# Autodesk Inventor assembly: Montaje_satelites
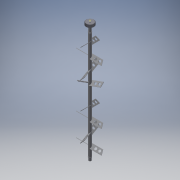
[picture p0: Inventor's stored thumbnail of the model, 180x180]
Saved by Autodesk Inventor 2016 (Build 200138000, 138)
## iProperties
Created: 2016-10
Part Number: Montaje_satelites
Document SubType Name: Assembly
Designer: Ingenieria
Author: Ingenieria
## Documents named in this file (7)
- C:\Users\ingenieria\Desktop\INGENIERIA\Proyectos\2016\Enfriador_4\Planos\Montaje_satelites.iam
- C:\Users\ingenieria\Desktop\INGENIERIA\Proyectos\2016\Enfriador_4\Planos\tubo_mecanico_satelites.ipt
- C:\Users\ingenieria\Desktop\INGENIERIA\Proyectos\2016\Enfriador_4\Planos\eje_inferior satelites.ipt
- C:\Users\ingenieria\Desktop\INGENIERIA\Proyectos\2016\Enfriador_4\Planos\eje_superior_satelites.ipt
- C:\Users\ingenieria\Desktop\INGENIERIA\Proyectos\2016\Enfriador_4\Planos\pala_1.ipt
- pala.ipt
- C:\Users\ingenieria\Desktop\INGENIERIA\Proyectos\2016\Enfriador_4\Planos\Montaje_satelites\Design Accelerator\Spur Gears1.iam
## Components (20 placed, 5 different names)
1. tubo_mecanico_satelites:1 — Insert:1, Insert:2, Mate:1, Mate:2, Cylindrical:1, Cylindrical:2, Cylindrical:3, Cylindrical:4, Cylindrical:5, Cylindrical:6, Cylindrical:7, Cylindrical:8, Cylindrical:9, Cylindrical:10, Cylindrical:11, Cylindrical:12, Cylindrical:13, Cylindrical:14, Cylindrical:15, Cylindrical:16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
2. eje_inferior satelites:1 — Insert:2, Mate:19
3. eje_superior_satelites:1 — Insert:1, Mate:4, Mate:6, Mate:8, Mate:10, Mate:16, Mate:18
4. pala:1 — Cylindrical:2, Angle:1, Mate:3, Angle:2
5. pala:2 — Cylindrical:1, Angle:1, Mate:3, Mate:4
6. pala:3 — Cylindrical:3, Angle:3, Mate:5, Mate:6
7. pala:4 — Cylindrical:4, Angle:3, Mate:5, Angle:9
8. pala:5 — Cylindrical:5, Angle:5, Mate:7
9. pala:6 — Cylindrical:6, Angle:5, Mate:7, Mate:8, Angle:10
10. pala:7 — Cylindrical:7, Angle:7, Mate:9
11. pala:8 — Cylindrical:8, Angle:7, Mate:9, Mate:10, Angle:8, Flush:4
12. pala:9 — Cylindrical:9, Angle:11, Mate:11, Angle:12, Angle:16, Flush:1, Flush:4
13. pala:10 — Cylindrical:10, Angle:11, Mate:11
14. pala:11 — Cylindrical:12, Angle:13, Mate:12
15. pala:12 — Cylindrical:11, Angle:13, Mate:12, Angle:17, Flush:1, Flush:2
16. pala:13 — Cylindrical:14, Angle:14, Mate:13
17. pala:14 — Cylindrical:13, Angle:14, Mate:13, Angle:18, Flush:2, Flush:3
18. pala:15 — Cylindrical:16, Angle:15, Mate:14
19. pala:16 — Cylindrical:15, Angle:15, Mate:14, Angle:19, Flush:3
20. Spur Gears:1 [sub-assembly] — Mate:15, Mate:16, Mate:17
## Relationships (59: Mate 20, Angle 17, CylindricalJoint 16, Flush 4, Insert 2)
- Insert:1: tubo_mecanico_satelites:1 ↔ eje_superior_satelites:1
- Insert:2: tubo_mecanico_satelites:1 ↔ eje_inferior satelites:1
- Mate:1: tubo_mecanico_satelites:1
- Mate:2: tubo_mecanico_satelites:1
- Cylindrical:1: tubo_mecanico_satelites:1 ↔ pala:2
- Cylindrical:2: tubo_mecanico_satelites:1 ↔ pala:1
- Angle:1: pala:1 ↔ pala:2
- Mate:3: pala:1 ↔ pala:2
- Mate:4: eje_superior_satelites:1 ↔ pala:2
- Angle:2: pala:1
- Cylindrical:3: tubo_mecanico_satelites:1 ↔ pala:3
- Cylindrical:4: tubo_mecanico_satelites:1 ↔ pala:4
- Angle:3: pala:3 ↔ pala:4
- Mate:5: pala:3 ↔ pala:4
- Mate:6: eje_superior_satelites:1 ↔ pala:3
- Cylindrical:5: tubo_mecanico_satelites:1 ↔ pala:5
- Cylindrical:6: tubo_mecanico_satelites:1 ↔ pala:6
- Angle:5: pala:5 ↔ pala:6
- Mate:7: pala:5 ↔ pala:6
- Mate:8: eje_superior_satelites:1 ↔ pala:6
- Cylindrical:7: tubo_mecanico_satelites:1 ↔ pala:7
- Cylindrical:8: tubo_mecanico_satelites:1 ↔ pala:8
- Angle:7: pala:7 ↔ pala:8
- Mate:9: pala:7 ↔ pala:8
- Mate:10: eje_superior_satelites:1 ↔ pala:8
- Angle:8: pala:8
- Angle:9: pala:4
- Angle:10: pala:6
- Cylindrical:9: tubo_mecanico_satelites:1 ↔ pala:9
- Cylindrical:10: tubo_mecanico_satelites:1 ↔ pala:10
- Angle:11: pala:9 ↔ pala:10
- Mate:11: pala:9 ↔ pala:10
- Angle:12: pala:9
- Cylindrical:11: tubo_mecanico_satelites:1 ↔ pala:12
- Cylindrical:12: tubo_mecanico_satelites:1 ↔ pala:11
- Cylindrical:13: tubo_mecanico_satelites:1 ↔ pala:14
- Cylindrical:14: tubo_mecanico_satelites:1 ↔ pala:13
- Cylindrical:15: tubo_mecanico_satelites:1 ↔ pala:16
- Cylindrical:16: tubo_mecanico_satelites:1 ↔ pala:15
- Angle:13: pala:11 ↔ pala:12
- Mate:12: pala:11 ↔ pala:12
- Angle:14: pala:13 ↔ pala:14
- Mate:13: pala:13 ↔ pala:14
- Angle:15: pala:15 ↔ pala:16
- Mate:14: pala:15 ↔ pala:16
- Angle:16: pala:9
- Angle:17: pala:12
- Angle:18: pala:14
- Angle:19: pala:16
- Flush:1: pala:9 ↔ pala:12
- Flush:2: pala:12 ↔ pala:14
- Flush:3: pala:14 ↔ pala:16
- Flush:4: pala:8 ↔ pala:9
- Mate:15: Spur Gears:1
- Mate:16: eje_superior_satelites:1 ↔ Spur Gears:1
- Mate:17: Spur Gears:1
- Mate:18: eje_superior_satelites:1
- Mate:19: eje_inferior satelites:1
- Mate:20: tubo_mecanico_satelites:1
